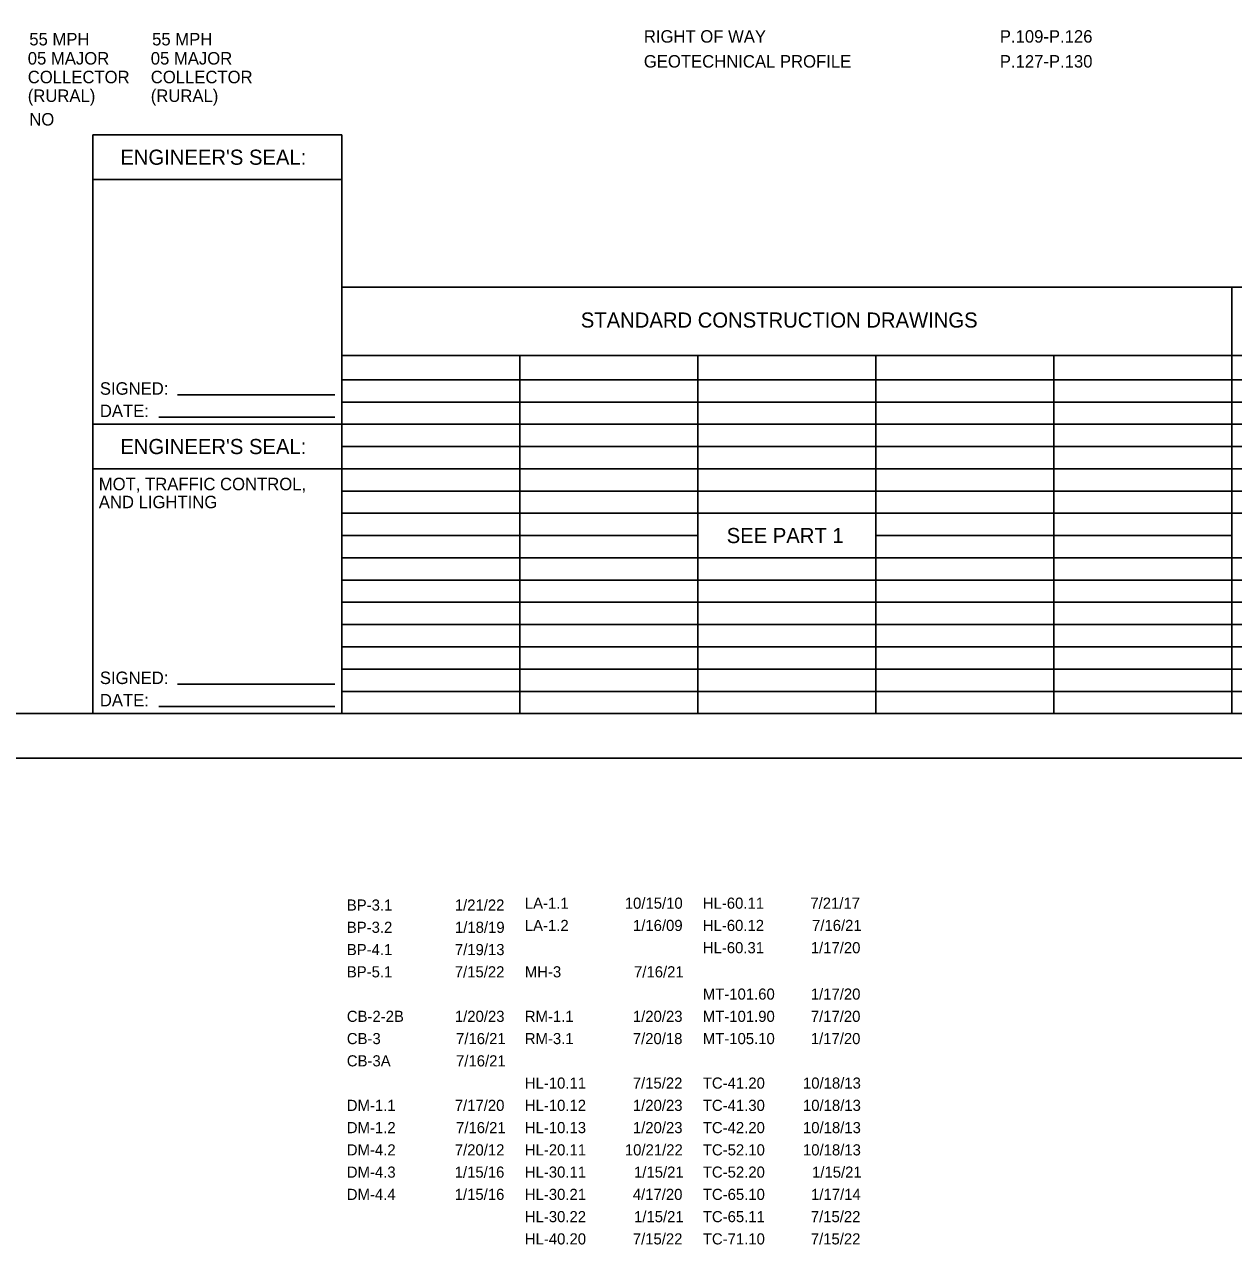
# Model space of a CAD drawing. Extents: x 0 to 72, y -85 to 22.
# Drawn here: x 7.68 to 21.27, y -5.46 to 8.24 of the extents above; entities that cross this region are included whole.
import ezdxf

# ---------------------------------------------------------------- set-up
doc = ezdxf.new("R2010")
doc.units = 0
for name, color, linetype in [('Default', 7, 'Continuous'), ('GM_X_Adjacent_County', 7, 'Continuous'), ('GM_X_County', 7, 'Continuous'), ('GM_X_Section', 7, 'Continuous'), ('GM_X_Township', 7, 'Continuous')]:
    doc.layers.add(name, color=color, linetype=linetype)

msp = doc.modelspace()

# ---------------------------------------------------------------- linework, layer by layer
at = {"layer": 'GM_X_Adjacent_County'}
for p, q in [((9.401, 4.082), (11.171, 4.082)), ((9.193, 3.831), (11.171, 3.831)), ((9.401, 0.832), (11.171, 0.832)), ((9.193, 0.581), (11.171, 0.581))]:
    msp.add_line(p, q, dxfattribs=at)
at = {"layer": 'GM_X_County'}
msp.add_lwpolyline([(1.5, 21.5), (33.5, 21.5), (33.5, 0.5), (1.5, 0.5)], close=True, dxfattribs=at)
at = {"layer": 'GM_X_Section'}
msp.add_lwpolyline([(0, 0), (34, 0), (34, 22), (0, 22)], close=True, dxfattribs=at)
at = {"layer": 'GM_X_Township'}
for p, q in [((8.45, 3.75), (8.45, 7)), ((8.45, 7), (11.25, 7)), ((11.25, 5.292), (11.25, 7)), ((8.45, 6.5), (11.25, 6.5)), ((11.25, 5.292), (24.7, 5.292)), ((11.25, 0.5), (11.25, 5.292)), ((21.25, 0.5), (21.25, 5.292)), ((11.25, 4.521), (24.7, 4.521)), ((13.25, 0.5), (13.25, 4.521)), ((15.25, 0.5), (15.25, 4.521)), ((17.25, 0.5), (17.25, 4.521)), ((19.25, 0.5), (19.25, 4.521)), ((11.25, 4.25), (24.7, 4.25)), ((11.25, 4), (24.7, 4)), ((8.45, 0.5), (8.45, 3.75)), ((8.45, 3.75), (11.25, 3.75)), ((11.25, 3.75), (24.7, 3.75)), ((11.25, 3.5), (24.7, 3.5)), ((8.45, 3.25), (11.25, 3.25)), ((11.25, 3.25), (24.7, 3.25)), ((11.25, 3), (24.7, 3)), ((11.25, 2.75), (24.7, 2.75)), ((11.25, 2.5), (15.25, 2.5)), ((17.25, 2.5), (21.25, 2.5)), ((11.25, 2.25), (24.7, 2.25)), ((11.25, 2), (24.7, 2)), ((11.25, 1.75), (24.7, 1.75)), ((11.25, 1.5), (24.7, 1.5)), ((11.25, 1.25), (24.7, 1.25)), ((11.25, 1), (24.7, 1)), ((11.25, 0.75), (24.7, 0.75))]:
    msp.add_line(p, q, dxfattribs=at)

# ---------------------------------------------------------------- texts
at = {"layer": 'Default'}
for s, p in [('BP-3.1', (11.305, -1.713)), ('1/21/22', (12.518, -1.713)), ('LA-1.1', (13.305, -1.692)), ('10/15/10', (14.428, -1.692)), ('HL-60.11', (15.305, -1.692)), ('7/21/17', (16.513, -1.692)), ('BP-3.2', (11.305, -1.963)), ('1/18/19', (12.52, -1.963)), ('LA-1.2', (13.305, -1.942)), ('1/16/09', (14.52, -1.942)), ('HL-60.12', (15.305, -1.942)), ('7/16/21', (16.532, -1.942)), ('BP-4.1', (11.305, -2.213)), ('7/19/13', (12.519, -2.213)), ('HL-60.31', (15.305, -2.192)), ('1/17/20', (16.518, -2.192)), ('BP-5.1', (11.305, -2.463)), ('7/15/22', (12.518, -2.463)), ('MH-3', (13.305, -2.463)), ('7/16/21', (14.532, -2.463)), ('MT-101.60', (15.305, -2.713)), ('1/17/20', (16.518, -2.713)), ('CB-2-2B', (11.305, -2.963)), ('1/20/23', (12.519, -2.963)), ('RM-1.1', (13.305, -2.963)), ('1/20/23', (14.519, -2.963)), ('MT-101.90', (15.305, -2.963)), ('7/17/20', (16.518, -2.963)), ('CB-3', (11.305, -3.213)), ('7/16/21', (12.532, -3.213)), ('RM-3.1', (13.305, -3.213)), ('7/20/18', (14.518, -3.213)), ('MT-105.10', (15.305, -3.213)), ('1/17/20', (16.518, -3.213)), ('CB-3A', (11.305, -3.463)), ('7/16/21', (12.532, -3.463)), ('HL-10.11', (13.305, -3.713)), ('7/15/22', (14.518, -3.713)), ('TC-41.20', (15.305, -3.713)), ('10/18/13', (16.43, -3.713)), ('7/17/20', (12.518, -3.963)), ('HL-10.12', (13.305, -3.963)), ('1/20/23', (14.519, -3.963)), ('TC-41.30', (15.305, -3.963)), ('10/18/13', (16.43, -3.963)), ('DM-1.1', (11.305, -3.963)), ('DM-1.2', (11.305, -4.213)), ('7/16/21', (12.532, -4.213)), ('HL-10.13', (13.305, -4.213)), ('1/20/23', (14.519, -4.213)), ('TC-42.20', (15.305, -4.213)), ('10/18/13', (16.43, -4.213)), ('DM-4.2', (11.305, -4.463)), ('7/20/12', (12.518, -4.463)), ('HL-20.11', (13.305, -4.463)), ('10/21/22', (14.429, -4.463)), ('TC-52.10', (15.305, -4.463)), ('10/18/13', (16.43, -4.463)), ('DM-4.3', (11.305, -4.713)), ('1/15/16', (12.517, -4.713)), ('HL-30.11', (13.305, -4.713)), ('1/15/21', (14.532, -4.713)), ('TC-52.20', (15.305, -4.713)), ('1/15/21', (16.532, -4.713)), ('DM-4.4', (11.305, -4.963)), ('1/15/16', (12.517, -4.963)), ('HL-30.21', (13.305, -4.963)), ('4/17/20', (14.518, -4.963)), ('TC-65.10', (15.305, -4.963)), ('1/17/14', (16.521, -4.963)), ('HL-30.22', (13.305, -5.213)), ('1/15/21', (14.532, -5.213)), ('TC-65.11', (15.305, -5.213)), ('7/15/22', (16.518, -5.213)), ('HL-40.20', (13.305, -5.463)), ('7/15/22', (14.518, -5.463)), ('TC-71.10', (15.305, -5.463)), ('7/15/22', (16.518, -5.463))]:
    msp.add_text(s, height=0.125, dxfattribs=at).set_placement(p)
at = {"layer": 'GM_X_Adjacent_County'}
for s, height, p in [('55 MPH', 0.14, (7.737, 8.006)), ('     55 MPH', 0.14, (8.857, 8.006)), ('RIGHT OF WAY', 0.14, (14.642, 8.037)), ('P.109-P.126', 0.14, (18.642, 8.037)), ('05 MAJOR ', 0.14, (7.72, 7.791)), ('05 MAJOR ', 0.14, (9.102, 7.791)), ('GEOTECHNICAL PROFILE', 0.14, (14.642, 7.757)), ('P.127-P.130', 0.14, (18.642, 7.757)), ('COLLECTOR ', 0.14, (7.72, 7.581)), ('COLLECTOR ', 0.14, (9.102, 7.581)), ('(RURAL)', 0.14, (7.72, 7.371)), ('(RURAL)', 0.14, (9.102, 7.371)), ('NO', 0.14, (7.737, 7.106)), ("ENGINEER'S SEAL:", 0.17, (8.76, 6.665)), ('STANDARD CONSTRUCTION DRAWINGS', 0.17, (13.934, 4.836)), ('SIGNED:', 0.14, (8.53, 4.082)), ('DATE:', 0.14, (8.53, 3.831)), ("ENGINEER'S SEAL:", 0.17, (8.76, 3.415)), ('MOT, TRAFFIC CONTROL, ', 0.14, (8.518, 3.009)), ('AND LIGHTING', 0.14, (8.518, 2.807)), ('SEE PART 1', 0.17, (15.573, 2.415)), ('SIGNED:', 0.14, (8.53, 0.832)), ('DATE:', 0.14, (8.53, 0.581))]:
    msp.add_text(s, height=height, dxfattribs=at).set_placement(p)

doc.saveas('drawing.dxf')
